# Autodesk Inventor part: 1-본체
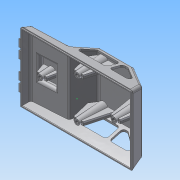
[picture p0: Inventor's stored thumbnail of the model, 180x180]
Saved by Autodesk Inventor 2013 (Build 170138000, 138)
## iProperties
Created: 2015-05
Part Number: 1-본체
Material: ABS 플라스틱
Document SubType Name: Modeling
Designer: Administrator
Mass: 267.523 g
Surface Area: 335.97 cm^2
Volume: 34.0793 cm^3
Density: 7.85 g/cm^3
Author: Administrator
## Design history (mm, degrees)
sketch "스케치1"
  geometry: L1 (-61, 0)-(61, 0); L2 (-61, 0)-(-58.588, 9); L3 (-58.588, 9)-(-19, 11.075); L4 (-19, 11.075)-(-6.549, 31); L5 (-6.549, 31)-(31, 31); L6 (31, 31)-(57.412, 13.392); L7 (57.412, 13.392)-(61, 0); 3 further points
  constraints: 14 end point, 1 coincident, 1 horizontal, 1 midpoint, 1 parallel, 1 point on line, 1 vertical alignment
  dimensions: "d4" = 122 distance of L1.start L1.end; "d6" = 105 deg angle of L1 L2; "d10" = 31 vertical distance of L1.end L5.end; "d12" = 9 distance from line of L1 L2.end; "d13" = 125 deg angle of L4 L3; "d14" = 105 deg angle of L1 L7; "d16" = 3 deg angle of L1 L3; "d39" = 30 horizontal distance of L1.end L5.end; "d46" = 20 vertical distance of point (61, 11) L5.end; "d55" = 42 horizontal distance of L3.end L1.start
extrude "돌출1" new body sketch "스케치1" stored distance "d17" = 76; taper "d18" = 0 deg
sketch "스케치5"
  geometry: L1 (0, 76)-(0, 0) reference; L2 (8.121, 51)-(28.121, 51); L3 (28.121, 51)-(28.121, 25); L4 (28.121, 25)-(8.121, 25); L5 (8.121, 25)-(8.121, 51); L6 (-2.879, 0)-(-2.879, 76) reference; 3 further points
  constraints: 8 end point, 2 midpoint, 2 parallel, 1 horizontal, 1 horizontal alignment, 1 perpendicular
  dimensions: "d57" = 26 distance of L2.end L3.end; "d59" = 20 distance of L2.start L2.end; "d97" = 11 distance between parallel lines of L5 L6
extrude "돌출3" join sketch "스케치5" distance "d61" = 5; taper "d62" = 0 deg
sketch "스케치2"
  geometry: L1 (0, 38)-(0, -38) reference; L2 (0, 38)-(31, 29.694); L3 (31, -29.694)-(0, -38); L4 (31, -38)-(31, 38) reference; L5 (11.075, -38)-(31, -38) reference; L6 (0, -38)-(9, -38) reference; L7 (9, -38)-(11.075, -38) reference; L8 (31, 38)-(11.075, 38) reference; L9 (9, 38)-(0, 38) reference; L10 (11.075, 38)-(9, 38) reference; 1 further point
  constraints: 4 end point, 2 point on line
  dimensions: "d19" = 105 deg angle of L1 L3; "d20" = 105 deg angle of L1 L2
extrude "돌출2" cut sketch "스케치2" stored distance "d23" = 76; taper "d24" = 0 deg
feature "쉘1" dims "d56" = 2
sketch "스케치6"
  geometry: L1 (119.929, -2.071)-(119.929, -73.929) reference; L2 (119.929, -73.929)-(2.071, -73.929) reference; L3 (2.071, -73.929)-(2.071, -2.071) reference; L4 (2.071, -2.071)-(119.929, -2.071) reference; L5 (122, -76)-(122, 0) reference; L6 (0, 0)-(122, 0) reference; L7 (0, 0)-(0, -76) reference; L8 (122, -76)-(0, -76) reference; L9 (121, -1)-(121, -75); L10 (121, -75)-(1, -75); L11 (1, -75)-(1, -1); L12 (1, -1)-(121, -1); 1 further point
  constraints: 8 end point, 3 other
  dimensions: "d63" = 1 distance between parallel lines of L6 L12
extrude "돌출4" join sketch "스케치6" distance "d64" = 1; taper "d65" = 0 deg
sketch "스케치7"
  geometry: L1 (-19, 11.075)-(-6.549, 31) reference; L2 (-6.549, 31)-(31, 31) reference; L3 (31, 31)-(57.412, 13.392) reference; L4 (-13.151, 11)-(-3.778, 26); L5 (-3.778, 26)-(20.849, 26); L6 (20.849, 26)-(20.849, 11); L7 (20.849, 11)-(-13.151, 11); L8 (23.986, 26)-(23.986, 11); L9 (23.986, 11)-(51.986, 11); L10 (51.986, 11)-(29.486, 26); L11 (29.486, 26)-(23.986, 26); 1 further point
  constraints: 16 end point, 4 parallel, 4 perpendicular
  dimensions: "d66" = 34 distance of L6.end L4.start; "d68" = 5 distance between parallel lines of L2 L5; "d69" = 5 distance between parallel lines of L1 L4; "d70" = 15 vertical distance of L4.start L4.end; "d71" = 28 distance of L8.end L9.end; "d72" = 5 distance between parallel lines of L3 L10; "d73" = 5 distance from line of L2 L10.end; "d74" = 15 distance of L8.start L8.end
extrude "돌출5" cut sketch "스케치7" stored distance "d75" = 1; taper "d76" = 0 deg
node "작업 평면1"
sketch "스케치9"
  geometry: A1 r 4 centre (0, -21) between (0, -17) and (0, -25); A2 r 4 centre (0, -10) between (0, -6) and (0, -14); A3 r 4 centre (0, 10) between (0, 14) and (0, 6); A4 r 4 centre (0, 21) between (0, 25) and (0, 17); 3 further points
  constraints: 8 point on circle, 4 centre point, 3 equal radius, 13 other
  dimensions: "d78" = 11 distance of A2.centre A1.centre; "d80" = 4 radius of A1; "d81" = 20 distance of A3.centre A2.centre; "d82" = 10 distance of point (0, 0) A2.centre; "d83" = 11 distance of A4.centre A3.centre
extrude "돌출6" join sketch "스케치9" stored distance "d84" = 1; taper "d85" = 0 deg
sketch "스케치10"
  geometry: L1 (122, -76)-(122, 0) reference; C1 r 3 at (21, -38); C2 r 3 at (101, -38); C3 r 3 at (61, -60); C4 r 3 at (61, -16); 1 further point
  constraints: 4 centre point, 2 horizontal alignment, 2 vertical alignment
  dimensions: "d86" = 6 diameter of C1; "d88" = 6 diameter of C2; "d89" = 40 distance of point (61, -38) C1.centre; "d90" = 21 distance from line of L1 C2.centre; "d91" = 6 diameter of C3; "d92" = 22 distance of point (61, -38) C3.centre; "d93" = 6 diameter of C4; "d94" = 22 distance of point (61, -38) C4.centre
extrude "돌출7" join sketch "스케치10" stored distance "d95" = 1; taper "d96" = 4 deg
sketch "스케치14"
  geometry: L1 (23.986, 26)-(29.486, 26) reference; L2 (29.486, 26)-(51.986, 11) reference; L3 (51.986, 11)-(23.986, 11) reference; L4 (23.986, 11)-(23.986, 26) reference; L5 (-3.778, 26)-(20.849, 26) reference; L6 (20.849, 26)-(20.849, 11) reference; L7 (20.849, 11)-(-13.151, 11) reference; L8 (-13.151, 11)-(-3.778, 26) reference; L9 (-19, 11.075)-(-6.549, 31) reference; L10 (-58.588, 9)-(-19, 11.075) reference; L11 (-61, 0)-(-58.588, 9) reference; L12 (-61, 0)-(61, 0) reference; L13 (57.412, 13.392)-(61, 0) reference; L14 (31, 31)-(57.412, 13.392) reference; L15 (-6.549, 31)-(31, 31) reference; L16 (37, 0)-(35.196, 25.799) reference; L17 (43, 0)-(44.376, 19.679) reference; L18 (30.394, 29)-(55.675, 12.146) reference; L19 (35, 2)-(36.86, 2); L20 (43.14, 2)-(45, 2); L21 (30.394, 29)-(35, 2); L22 (45, 2)-(47.803, 17.394); 1 further point
  constraints: 8 end point, 3 point on line, 2 collinear, 2 parallel
  dimensions: "d118" = 10 distance of L19.start L20.end; "d121" = 2 distance between parallel lines of L12 L20; "d124" = 20 deg angle of L21 L22
extrude "돌출8" join sketch "스케치14" stored distance "d125" = 4; taper "d126" = 5 deg
sketch "스케치15"
  geometry: 1 further point
fillet "모깎기1" dims "d127" = 3
sketch "스케치16"
  geometry: L1 (-30.663, 13.468)-(-50.636, 12.421) reference; L2 (-48.534, 10.528)-(-48.639, 12.526) reference; L3 (-32.556, 11.366)-(-32.661, 13.363) reference; L4 (-43, 0)-(-43.893, 12.774) reference; L5 (-37, 0)-(-36.078, 13.184) reference; L6 (-48.639, 12.526)-(-45, 2); L7 (-35, 2)-(-32.661, 13.363); L8 (-61, 0)-(61, 0) reference; L9 (-45, 2)-(-43.14, 2); L10 (-36.86, 2)-(-35, 2); 1 further point
  constraints: 8 end point, 3 collinear, 2 point on line, 1 parallel
  dimensions: "d129" = 2 distance from line of L8 L7.start; "d130" = 10 distance of L7.start L6.end
extrude "돌출9" join sketch "스케치16" stored distance "d131" = 4; taper "d132" = 5 deg
node "작업 평면2"
sketch "스케치17"
  geometry: L1 (-5.441, 29)-(30.394, 29) reference; L2 (-17.856, 9.132)-(-5.441, 29) reference; L3 (-3, 0)-(-5.028, 29) reference; L4 (3, 0)-(5.028, 29) reference; L5 (12.477, 29)-(5, 2); L6 (-61, 0)-(61, 0) reference; L7 (5, 2)-(3.14, 2); L8 (-3.14, 2)-(-5, 2); L9 (-5, 2)-(-9.815, 22); 1 further point
  constraints: 8 end point, 3 collinear, 3 point on line, 1 midpoint, 1 parallel
  dimensions: "d134" = 2 distance between parallel lines of L6 L7; "d138" = 10 distance of L5.end L8.end; "d141" = 76.4642 deg angle of L1 L9
extrude "돌출10" join sketch "스케치17" stored distance "d142" = 4; taper "d143" = 5 deg
sketch "스케치12"
  geometry: C1 r 3 at (0, 0) reference; C2 r 3 at (40, 22) reference; C3 r 3 at (80, 0) reference; C4 r 3 at (40, -22) reference; 5 further points
  constraints: 4 coincident
hole "구멍1" sketch "스케치12" at (0, 0), (40, 22), (40, -22), (80, 0) diameter "d106" = 3.242; stored, may be unused: countersink angle "d110" = 90 deg, drill point angle "d112" = 118 deg; dims "d107" = 9, "d108" = 4, "d109" = 2, "d111" = 11
sketch "스케치13"
  geometry: L1 (67.549, 67.694)-(67.549, -8.306) reference; 3 further points
  constraints: 1 horizontal alignment, 1 midpoint, 1 other
  dimensions: "d113" = 50 distance from line of L1 point (17.549, 29.694)
feature "엠보싱1" sketch "스케치13" dims "d114" = 0.5, "d115" = 0
fillet "모깎기2" dims "d144" = 3
fillet "모깎기3" dims "d145" = 3
fillet "모깎기4" dims "d146" = 3
fillet "모깎기5" dims "d147" = 3
fillet "모깎기6" dims "d148" = 3
fillet "모깎기7" dims "d149" = 3
fillet "모깎기8" dims "d150" = 3
node "솔리드1"
mirror "대칭1"
node "투영된 루프2"
other parameters: "d77" = -63, "d120" = 2, "d133" = 22
